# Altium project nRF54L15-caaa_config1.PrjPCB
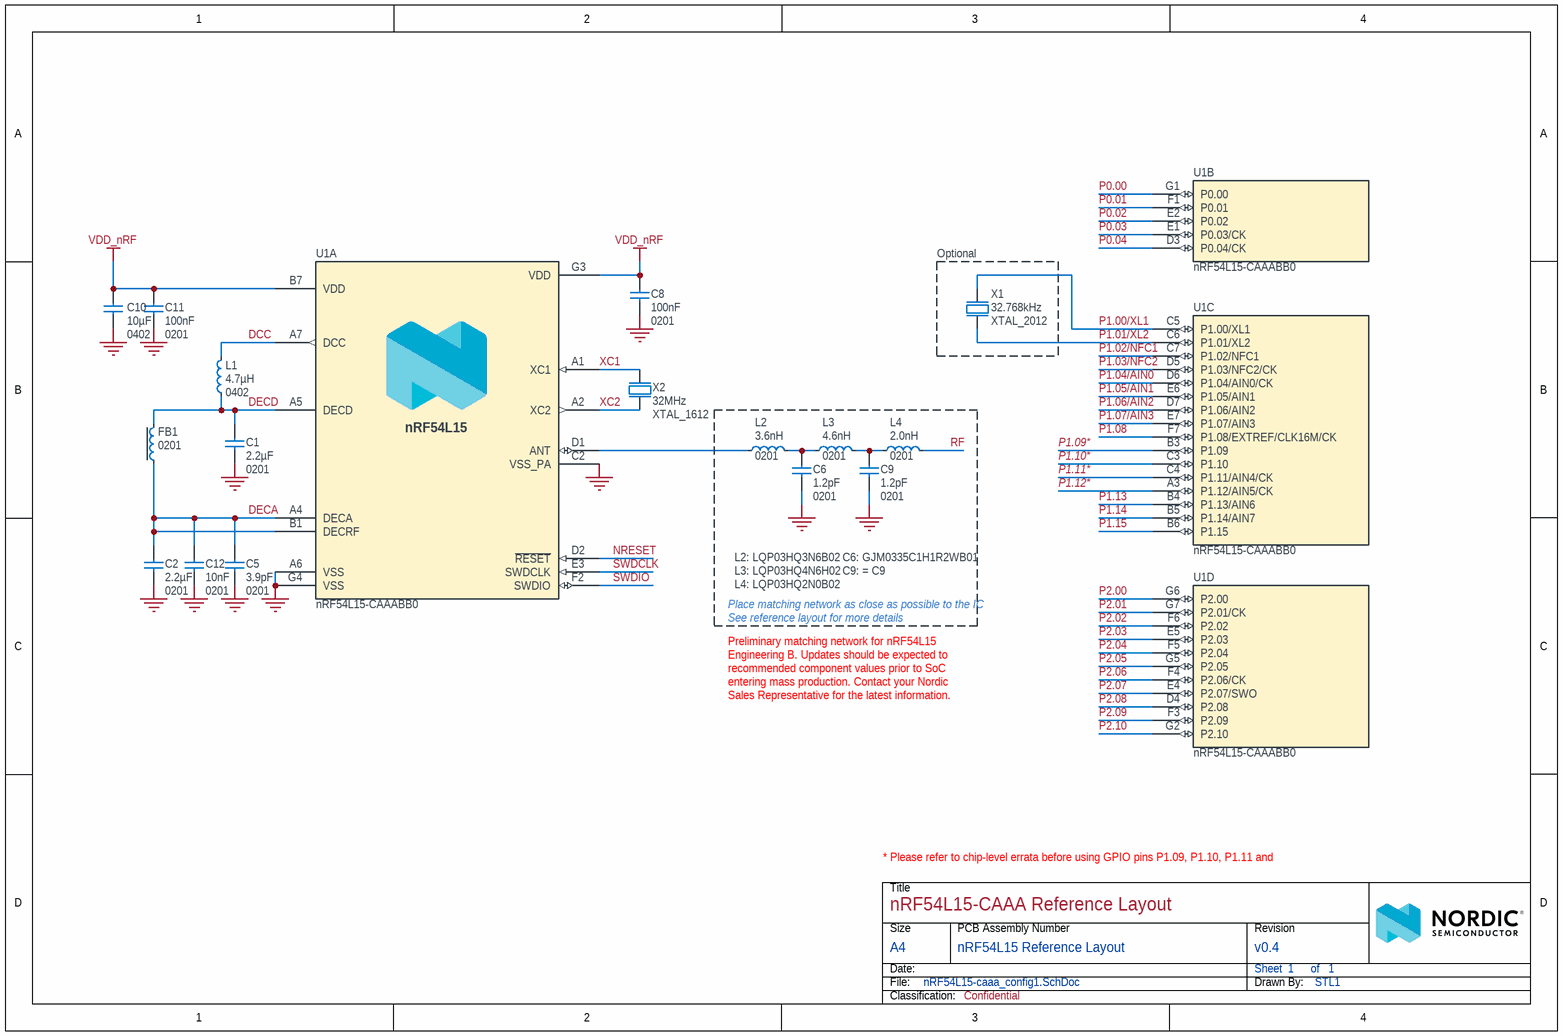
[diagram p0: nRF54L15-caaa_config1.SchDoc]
BoardTitle: =Title; Classification: Confidential; Designer: =DrawnBy; Device: nRF54L15-CAAA; DrawnBy: STL1; PCAName: nRF54L15 Reference Layout; PCARevision: =Revision; ProjectTitle: =Title; Revision: v0.4; Title: nRF54L15-CAAA Reference Layout
1 sheet, 17 parts. Net scope: strictly hierarchical (ports join the sheet entries above them; power ports are local).
Board file: nRF54L15-caaa_config1.PcbDoc

## Sheet nRF54L15-caaa_config1.SchDoc: nRF54L15-CAAA Reference Layout
size A4; Device: nRF54L15-CAAA; Organization: Nordic Semiconductor; DocumentNumber: 1; SheetNumber: 1; SheetTotal: 1; CompanyName: Nordic Semiconductor; DocumentSize: A4

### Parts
C1  2.2µF  Footprint Doc: 0201  [CAPC0603X03L_C]
C2  2.2µF  Footprint Doc: 0201  [CAPC0603X03L_C]
C5  3.9pF  Footprint Doc: 0201  [CAPC0603X03L_C]
C6  1.2pF  Footprint Doc: 0201  [CAPC0603X03L_C]
C8  100nF  Footprint Doc: 0201  [CAPC0603X03L_C]
C9  1.2pF  Footprint Doc: 0201  [CAPC0603X03L_C]
C10  10µF  Footprint Doc: 0402  [CAPC1005X04L]
C11  100nF  Footprint Doc: 0201  [CAPC0603X03L_C]
C12  10nF  Footprint Doc: 0201  [CAPC0603X03L_C]
FB1  Footprint Doc: 0201  [INDC0603X03L_C]  (hidden comment: 120R/0.2A)
L1  4.7µH  Footprint Doc: 0402  [INDC1005X04L]
L2  3.6nH  Footprint Doc: 0201  [INDC0603X03L_C]
L3  4.6nH  Footprint Doc: 0201  [INDC0603X03L_C]
L4  2.0nH  Footprint Doc: 0201  [INDC0603X03L_C]
U1  nRF54L15-CAAABB0  [BGA49C30P7x7_2245X2451X48]  (parts A,B,C,D of 4)
X1  32.768kHz  [XTAL_2012]
X2  32MHz  Footprint Doc: XTAL_1612  [BT-XTAL_1612]

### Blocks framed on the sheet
Optional: X1

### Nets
GND: C1.1 C2.1 C5.1 C6.1 C8.2 C9.1 C10.1 C11.2 C12.1 U1.A6(VSS) U1.C2(VSS_PA) U1.G4(VSS) X2.2(GND) X2.4(GND)
VDD_nRF: C8.1 C10.2 C11.1 U1.B7(VDD) U1.G3(VDD)
DCC: L1.1 U1.A7(DCC)
DECA: C2.2 C5.2 C12.2 FB1.2 U1.A4(DECA) U1.B1(DECRF)
DECD: C1.2 FB1.1 L1.2 U1.A5(DECD)
NRESET: U1.D2(~{RESET})
P0.00: U1.G1(P0.00)
P0.01: U1.F1(P0.01)
P0.02: U1.E2(P0.02)
P0.03: U1.E1(P0.03/CK)
P0.04: U1.D3(P0.04/CK)
P1.00/XL1: U1.C5(P1.00/XL1) X1.2(out)
P1.01/XL2: U1.C6(P1.01/XL2) X1.1(inp)
P1.02/NFC1: U1.C7(P1.02/NFC1)
P1.03/NFC2: U1.D5(P1.03/NFC2/CK)
P1.04/AIN0: U1.D6(P1.04/AIN0/CK)
P1.05/AIN1: U1.E6(P1.05/AIN1)
P1.06/AIN2: U1.D7(P1.06/AIN2)
P1.07/AIN3: U1.E7(P1.07/AIN3)
P1.08: U1.F7(P1.08/EXTREF/CLK16M/CK)
P1.09*: U1.B3(P1.09)
P1.10*: U1.C3(P1.10)
P1.11*: U1.C4(P1.11/AIN4/CK)
P1.12*: U1.A3(P1.12/AIN5/CK)
P1.13: U1.B4(P1.13/AIN6)
P1.14: U1.B5(P1.14/AIN7)
P1.15: U1.B6(P1.15)
P2.00: U1.G6(P2.00)
P2.01: U1.G7(P2.01/CK)
P2.02: U1.F6(P2.02)
P2.03: U1.E5(P2.03)
P2.04: U1.F5(P2.04)
P2.05: U1.G5(P2.05)
P2.06: U1.F4(P2.06/CK)
P2.07: U1.E4(P2.07/SWO)
P2.08: U1.D4(P2.08)
P2.09: U1.F3(P2.09)
P2.10: U1.G2(P2.10)
RF: L4.2
SWDCLK: U1.E3(SWDCLK)
SWDIO: U1.F2(SWDIO)
XC1: U1.A1(XC1) X2.1(inp)
XC2: U1.A2(XC2) X2.3(out)
NetC6_2: C6.2 L2.2 L3.1
NetC9_2: C9.2 L3.2 L4.1
NetL2_1: L2.1 U1.D1(ANT)

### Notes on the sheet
- L2: LQP03HQ3N6B02
- L3: LQP03HQ4N6H02
- C6: GJM0335C1H1R2WB01
- C9: = C9
- See reference layout for more details
- Place matching network as close as possible to the IC
- L4: LQP03HQ2N0B02
- Preliminary matching network for nRF54L15 Engineering B. Updates should be expected to recommended component values prior to SoC entering mass production. Contact your Nordic Sales Representative for the latest information.
- * Please refer to chip-level errata before using GPIO pins P1.09, P1.10, P1.11 and P1.12

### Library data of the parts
C1 C2 = C0201-2µ2-2.5V-X6T-GRM033D80E225ME47D: Capacitor, Ceramic, 2.2µF 2.5V X6T 0201,±20%; Manufacturer: Murata; Manufacturer Part Number: GRM033R61A225KE47; Part number NEMS: 100200527; Component Status: Active; Pad Count: 2; Note: 2.5V, 20%, X6T; Artikkelnr Noca: N.A.
C5 = C0201-3.9p-HQ-Murata: Capacitor, NP0, ±0.05pF, 25V; Manufacturer: Murata; Manufacturer Part Number: GJM0333C1E3R9WB01; Part number NEMS: 100200424; Component Status: Active; Pad Count: 2; Artikkelnr Noca: N.A.
C6 C9 = C0201-1.2p-HQ-Murata: Capacitor, NP0, ±0.05pF, 50V; Manufacturer: Murata; Manufacturer Part Number: GJM0335C1H1R2WB01D; Part number NEMS: 100200457; Component Status: Active; Pad Count: 2; Artikkelnr Noca: N.A.
C8 C11 = C0201-100n-10V-X7R: Capacitor, X7R, ±10%; Manufacturer: N.A.; Part number NEMS: 100200469; Note: 10V; Pad Count: 2; Component Status: Active
C10 = C0402-10µF-6.3V-X6S: Capacitor, X6S, ±20%, 6.3V; Manufacturer: N.A.; Part number NEMS: 100200478; Component Status: Active; Pad Count: 2
C12 = C0201-10n-6.3V-X7R: Capacitor, X7R, 6.3V; Manufacturer: Murata; Manufacturer Part Number: GRM033R70J103KA01D; Part number NEMS: 100200407; Component Status: Active; Pad Count: 2; Artikkelnr Noca: N.A.
FB1 = FB0201-120R@100M-200mA-BLM03AG121SN1D: Ferrite Bead, 120 Ohm @ 100MHz, 200mA, 500 mOhm Max; Manufacturer: Murata; Part number NEMS: 100300419; Component Status: Active; Pad Count: 2; Artikkelnr Noca: N.A.
L1 = L0402-4µ7-PLEA67BCA4R7M-1PT00: Inductor, 300mA, ±20%, 1.08R; Manufacturer: TDK Corporation; Part number NEMS: 100300441; Component Status: Active; Pad Count: 2; Note: Power Inductor ±20%; Artikkelnr Noca: N.A.
L2 = L0201-3n6-HQ-Murata: Inductor, 500mA, ±0.1ｎH, 170mOhm; Manufacturer: Murata; Manufacturer Part Number: LQP03HQ3N6B02; Part number NEMS: 100300223; Component Status: Active; Pad Count: 2; Note: -55°C ~ 125°C; Artikkelnr Noca: N.A.
L3 = L0201-4n6-HQ-Murata: Inductor, 400mA, ±3%, 250mOhm; Manufacturer: Murata; Manufacturer Part Number: LQP03HQ4N6H02; Part number NEMS: 100300500; Component Status: Active; Pad Count: 2; Note: -55°C ~ 125°C; Artikkelnr Noca: N.A.
L4 = L0201-2n0-HQ-Murata: Inductor, 600mA, ±0.1ｎH, 120mOhm; Manufacturer: Murata; Manufacturer Part Number: LQP03HQ2N0B02; Part number IPS: 00000001670; Part number NEMS: 100300207; Component Status: Active; Pad Count: 2; Note: -55°C ~ 125°C; Artikkelnr Noca: N.A.
U1 = nRF54L15-CAAABB0: Multi-protocol Bluetooth Low Energy, IEEE 802.15.4, ANT and 2.4GHz proprietary system-on-chip; Manufacturer: Nordic Semiconductor; Component Status: Active; Pad Count: 47; Note: N.A.
X1 = XTAL_SMD2012_32.768kHz_9pF_TXC: XTAL SMD 2012, 32.768kHz, 9pF, ±20ppm; Manufacturer: TXC Corporation; Manufacturer Part Number: 9HT11-32.768KDZC-T; Part number NEMS: 101600107; Component Status: Active; Pad Count: 2; Note: XTAL SMD 32.768kHz; Artikkelnr Noca: N.A.
X2 = XTAL_SMD1612_32MHz_8pF_Kyocera: XTAL SMD 1612, 32MHz, Cl=8pF, Tot: ±40ppm, Aging: ±1ppm/year; Manufacturer Part Number: CX1612DB32000D0WZRC3; Part number NEMS: 101600029; Component Status: Active; Pad Count: 4; Note: XTAL SMD 32.000MHz; Artikkelnr Noca: N.A.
